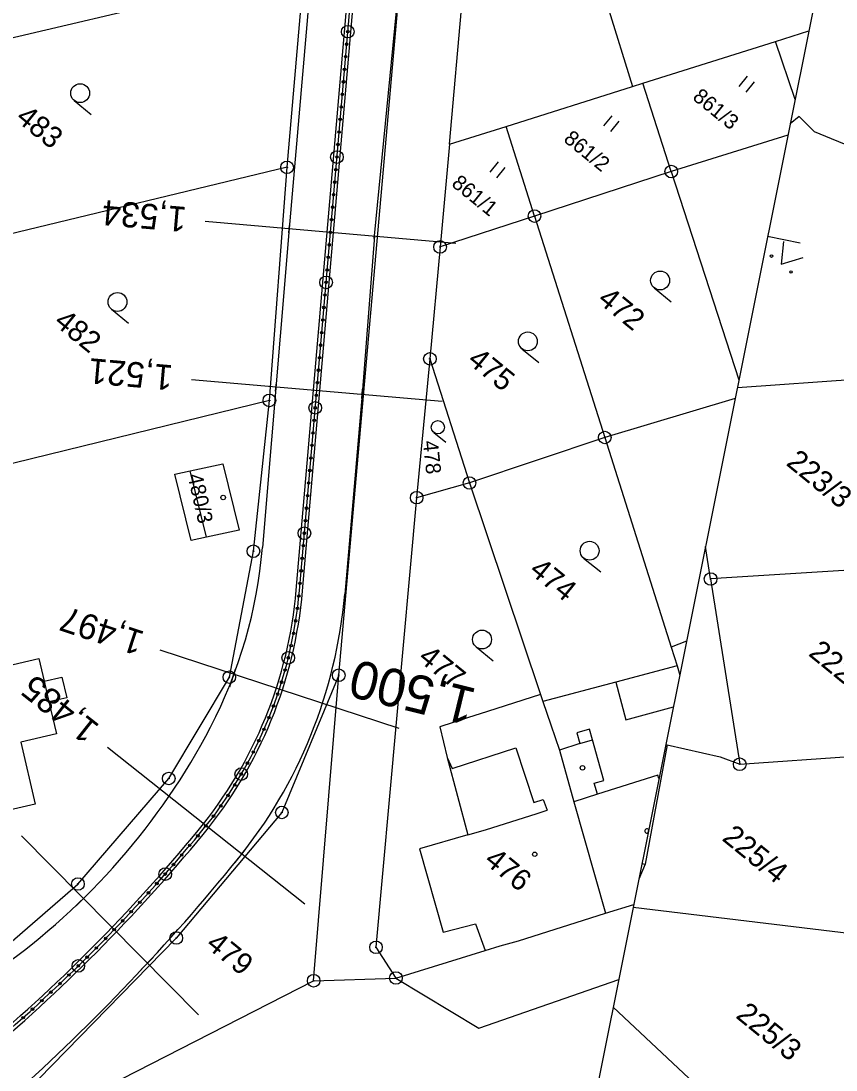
# Model space of a CAD drawing. Extents: x -548552 to -543113, y -1131925 to -1123599.
# Drawn here: x -548067.8 to -548003, y -1130269.7 to -1130186.3 of the extents above; entities that cross this region are included whole.
import ezdxf

# ---------------------------------------------------------------- set-up
doc = ezdxf.new("R2010")
doc.units = 0
for name, color, linetype in [('Hranice parcel', 7, 'Continuous'), ('Parcelní čísla', 7, 'Continuous'), ('Poz předměty', 7, 'Continuous'), ('Profile', 7, 'Continuous'), ('PROFILY', 7, 'Continuous'), ('STANIČENÍ', 7, 'Continuous'), ('STANIČENÍ PROFILY', 7, 'Continuous'), ('Vnitřní kresba', 7, 'Continuous'), ('Značky bodu BP', 7, 'Continuous'), ('Značky budov', 7, 'Continuous'), ('Značky kultur', 7, 'Continuous')]:
    doc.layers.add(name, color=color, linetype=linetype)

msp = doc.modelspace()

# ---------------------------------------------------------------- linework, layer by layer
at = {"layer": 'Hranice parcel'}
for p, q in [((-548033.748, -1130196.121), (-548032.291, -1130179.909)), ((-548045.268, -1130182.222), (-548085.244, -1130191.601)), ((-548046.64, -1130197.95), (-548045.268, -1130182.222)), ((-548007.844, -1130187.945), (-548005.181, -1130187.105)), ((-548018.386, -1130191.275), (-548007.844, -1130187.945)), ((-548006.276, -1130192.568), (-548007.844, -1130187.945)), ((-548029.238, -1130194.701), (-548019.184, -1130191.528)), ((-548019.184, -1130191.528), (-548018.386, -1130191.275)), ((-548016.113, -1130198.286), (-548018.386, -1130191.275)), ((-548033.748, -1130196.121), (-548029.238, -1130194.701)), ((-548026.982, -1130201.827), (-548029.238, -1130194.701)), ((-548006.844, -1130195.397), (-548016.113, -1130198.286)), ((-548001.454, -1130196.473), (-548004.739, -1130195.139)), ((-548033.748, -1130196.121), (-548034.486, -1130204.278)), ((-548046.64, -1130197.95), (-548075.622, -1130204.948)), ((-548048.046, -1130216.475), (-548046.64, -1130197.95)), ((-548016.113, -1130198.286), (-548026.982, -1130201.827)), ((-548016.113, -1130198.286), (-548010.742, -1130214.843)), ((-548026.982, -1130201.827), (-548034.486, -1130204.278)), ((-548026.982, -1130201.827), (-548021.396, -1130219.417)), ((-548034.486, -1130204.278), (-548035.291, -1130213.167)), ((-548035.291, -1130213.167), (-548036.346, -1130224.2)), ((-548035.291, -1130213.167), (-548032.144, -1130223.031)), ((-548010.86, -1130215.434), (-548000.239, -1130214.695)), ((-548048.046, -1130216.475), (-548075.117, -1130223.106)), ((-548011.035, -1130216.308), (-548021.396, -1130219.417)), ((-548021.396, -1130219.417), (-548032.144, -1130223.031)), ((-548021.396, -1130219.417), (-548016.126, -1130236.08)), ((-548032.144, -1130223.031), (-548036.346, -1130224.2)), ((-548032.144, -1130223.031), (-548026.511, -1130239.835)), ((-548012.988, -1130230.66), (-548013.395, -1130228.081)), ((-547988.024, -1130229.07), (-548012.988, -1130230.66)), ((-548012.988, -1130230.66), (-548010.674, -1130245.379)), ((-548014.904, -1130235.608), (-548016.126, -1130236.08)), ((-548016.126, -1130236.08), (-548015.655, -1130237.56)), ((-548044.53, -1130262.587), (-548042.539, -1130238.309)), ((-548026.511, -1130239.835), (-548026.327, -1130240.385)), ((-548010.674, -1130245.379), (-548001.577, -1130244.741)), ((-547998.027, -1130259.319), (-548019.145, -1130256.769)), ((-548037.992, -1130262.367), (-548030.915, -1130260.187)), ((-548072.972, -1130277.092), (-548044.53, -1130262.587)), ((-548044.53, -1130262.587), (-548037.992, -1130262.367))]:
    msp.add_line(p, q, dxfattribs=at)
for points in [[(-548042.539, -1130238.309), (-548033.342, -1130134.206), (-548027.481, -1130069.111), (-548024.869, -1130039.574), (-548023.736, -1130027.701), (-548024.259, -1130024.528), (-548026.746, -1130012.635), (-548032.196, -1129998.457), (-548039.765, -1129984.964)], [(-548032.291, -1130179.909), (-548023.886, -1130177.096), (-548025.091, -1130172.876), (-548012.83, -1130168.908), (-548008.896, -1130181.194), (-548021.189, -1130185.122), (-548019.184, -1130191.528)], [(-548004.739, -1130195.139), (-548005.938, -1130193.903), (-548006.665, -1130194.506)], [(-548082.316, -1130271.415), (-548063.263, -1130254.897), (-548056.045, -1130246.512), (-548051.23, -1130238.465), (-548049.317, -1130228.453), (-548048.046, -1130216.475)], [(-548054.347, -1130222.072), (-548051.739, -1130221.515), (-548050.447, -1130226.785), (-548053.056, -1130227.342), (-548054.259, -1130227.6), (-548055.558, -1130222.324), (-548054.347, -1130222.072)], [(-548036.346, -1130224.2), (-548039.577, -1130259.927), (-548037.992, -1130262.367)], [(-548067.804, -1130243.626), (-548066.662, -1130248.542), (-548076.655, -1130250.849), (-548079.17, -1130239.94), (-548069.191, -1130237.634), (-548066.358, -1130236.975), (-548065.947, -1130238.781), (-548064.53, -1130238.451), (-548064.154, -1130240.112), (-548065.564, -1130240.433), (-548064.972, -1130242.967), (-548067.804, -1130243.626)], [(-548015.655, -1130237.56), (-548020.521, -1130238.846), (-548026.327, -1130240.385)], [(-548015.655, -1130237.56), (-548015.443, -1130238.296)], [(-548042.539, -1130238.309), (-548047.062, -1130249.212), (-548055.446, -1130259.188), (-548072.972, -1130277.092)], [(-548026.511, -1130239.835), (-548030.723, -1130241.189), (-548032.305, -1130241.706), (-548034.501, -1130242.406), (-548033.926, -1130244.835), (-548032.279, -1130251), (-548036.119, -1130252.103), (-548034.227, -1130258.727), (-548031.664, -1130258.067), (-548030.915, -1130260.187)], [(-548026.327, -1130240.385), (-548025.697, -1130242.239), (-548025.006, -1130244.273), (-548023.849, -1130248.362), (-548021.352, -1130257.22)], [(-548016.433, -1130243.835), (-548018.185, -1130253.332), (-548018.691, -1130254.503)], [(-548016.548, -1130243.809), (-548016.433, -1130243.835)], [(-548016.433, -1130243.835), (-548012.227, -1130244.784), (-548010.674, -1130245.379)], [(-548021.352, -1130257.22), (-548019.096, -1130256.523)], [(-548030.915, -1130260.187), (-548029.709, -1130259.815), (-548028.264, -1130259.418), (-548021.352, -1130257.22)], [(-548020.732, -1130264.685), (-548009.966, -1130274.783)]]:
    msp.add_lwpolyline(points, dxfattribs=at)
at = {"layer": 'Poz předměty'}
for p, q in [((-548045.909, -1130231.549), (-548029.039, -1130036.611)), ((-548045.411, -1130231.592), (-548028.541, -1130036.654)), ((-548044.159, -1130175.947), (-548046.465, -1130202.821)), ((-548039.7, -1130203.406), (-548037.055, -1130176.562)), ((-548046.465, -1130202.821), (-548048.597, -1130228.168)), ((-548039.7, -1130203.406), (-548040.678, -1130215.988)), ((-548040.678, -1130215.988), (-548042.063, -1130231.874))]:
    msp.add_line(p, q, dxfattribs=at)
for centre, radius, start, end in [((-548086.208, -1130225.003), 37.743, 332.49077, 355.18998), ((-548080.53, -1130228.553), 34.75, 320.53715, 355.05376), ((-548080.53, -1130228.553), 35, 320.53715, 355.05376), ((-548080.53, -1130228.553), 35.25, 320.53715, 355.05376), ((-548080.737, -1130228.502), 38.82, 320.93302, 355.01788), ((-548100.597, -1130217.509), 53.966, 305.24777, 332.49077), ((-548157.702, -1130165.021), 134.709, 309.85025, 320.53715), ((-548157.702, -1130165.021), 134.959, 309.85025, 320.53715), ((-548157.702, -1130165.021), 135.209, 309.85025, 320.53715), ((-548177.245, -1130150.164), 163.121, 311.83002, 320.93302)]:
    msp.add_arc(centre, radius, start, end, dxfattribs=at)
at = {"layer": 'Profile'}
for p, q in [((-548003.516, -1130178.797), (-548026.625, -1130294.081)), ((-548003.516, -1130178.797), (-548026.625, -1130294.081)), ((-548003.516, -1130178.797), (-548026.625, -1130294.081)), ((-548005.871, -1130203.979), (-548008.46, -1130203.46))]:
    msp.add_line(p, q, dxfattribs=at)
at = {"layer": 'PROFILY'}
for points in [[(-548053.159, -1130202.241), (-548033.234, -1130203.966)], [(-548054.247, -1130214.813), (-548034.322, -1130216.538)], [(-548056.762, -1130236.298), (-548037.754, -1130242.518)], [(-548060.902, -1130244.034), (-548045.236, -1130256.466)], [(-548067.752, -1130251.081), (-548053.681, -1130265.295)]]:
    msp.add_lwpolyline(points, dxfattribs=at)
at = {"layer": 'STANIČENÍ'}
for p, q in [((-548045.66, -1130231.571), (-548028.79, -1130036.633)), ((-548046.494, -1130203.159), (-548046.443, -1130202.572)), ((-548039.718, -1130203.614), (-548039.686, -1130203.253)), ((-548047.552, -1130215.739), (-548047.493, -1130215.056)), ((-548040.706, -1130216.307), (-548040.643, -1130215.577)), ((-548063.411, -1130256.633), (-548062.393, -1130255.626)), ((-548058.229, -1130261.677), (-548057.282, -1130260.74))]:
    msp.add_line(p, q, dxfattribs=at)
for centre, radius in [((-548041.818, -1130187.172), 0.5), ((-548041.818, -1130187.172), 0.1), ((-548041.904, -1130188.168), 0.1), ((-548041.99, -1130189.165), 0.1), ((-548042.077, -1130190.161), 0.1), ((-548042.163, -1130191.157), 0.1), ((-548042.249, -1130192.153), 0.1), ((-548042.335, -1130193.15), 0.1), ((-548042.421, -1130194.146), 0.1), ((-548042.508, -1130195.142), 0.1), ((-548042.68, -1130197.135), 0.5), ((-548042.594, -1130196.138), 0.1), ((-548042.68, -1130197.135), 0.1), ((-548042.766, -1130198.131), 0.1), ((-548042.853, -1130199.127), 0.1), ((-548042.939, -1130200.124), 0.1), ((-548043.025, -1130201.12), 0.1), ((-548043.111, -1130202.116), 0.1), ((-548043.197, -1130203.112), 0.1), ((-548043.284, -1130204.109), 0.1), ((-548043.37, -1130205.105), 0.1), ((-548043.542, -1130207.097), 0.5), ((-548043.456, -1130206.101), 0.1), ((-548043.542, -1130207.097), 0.1), ((-548043.629, -1130208.094), 0.1), ((-548043.715, -1130209.09), 0.1), ((-548043.801, -1130210.086), 0.1), ((-548043.887, -1130211.083), 0.1), ((-548043.973, -1130212.079), 0.1), ((-548044.06, -1130213.075), 0.1), ((-548044.146, -1130214.071), 0.1), ((-548044.232, -1130215.068), 0.1), ((-548044.318, -1130216.064), 0.1), ((-548044.405, -1130217.06), 0.5), ((-548044.405, -1130217.06), 0.1), ((-548044.491, -1130218.057), 0.1), ((-548044.577, -1130219.053), 0.1), ((-548044.663, -1130220.049), 0.1), ((-548044.749, -1130221.045), 0.1), ((-548044.836, -1130222.042), 0.1), ((-548044.922, -1130223.038), 0.1), ((-548045.008, -1130224.034), 0.1), ((-548045.094, -1130225.03), 0.1), ((-548045.181, -1130226.027), 0.1), ((-548045.267, -1130227.023), 0.5), ((-548045.267, -1130227.023), 0.1), ((-548045.353, -1130228.019), 0.1), ((-548045.439, -1130229.016), 0.1), ((-548045.525, -1130230.012), 0.1), ((-548045.612, -1130231.008), 0.1), ((-548045.701, -1130232.004), 0.1), ((-548045.813, -1130232.998), 0.1), ((-548045.955, -1130233.988), 0.1), ((-548046.124, -1130234.973), 0.1), ((-548046.321, -1130235.953), 0.1), ((-548046.547, -1130236.928), 0.5), ((-548046.547, -1130236.928), 0.1), ((-548046.8, -1130237.895), 0.1), ((-548047.08, -1130238.855), 0.1), ((-548047.388, -1130239.806), 0.1), ((-548047.723, -1130240.748), 0.1), ((-548048.085, -1130241.681), 0.1), ((-548048.473, -1130242.602), 0.1), ((-548048.888, -1130243.512), 0.1), ((-548049.328, -1130244.41), 0.1), ((-548050.285, -1130246.166), 0.5), ((-548049.794, -1130245.295), 0.1), ((-548050.285, -1130246.166), 0.1), ((-548050.8, -1130247.023), 0.1), ((-548051.34, -1130247.865), 0.1), ((-548051.904, -1130248.691), 0.1), ((-548052.491, -1130249.5), 0.1), ((-548053.733, -1130251.068), 0.1), ((-548053.1, -1130250.293), 0.1), ((-548054.387, -1130251.824), 0.1), ((-548055.014, -1130252.595), 0.1), ((-548055.667, -1130253.354), 0.1), ((-548056.325, -1130254.108), 0.5), ((-548056.325, -1130254.108), 0.1), ((-548056.989, -1130254.859), 0.1), ((-548057.651, -1130255.596), 0.1), ((-548058.343, -1130256.354), 0.1), ((-548059.034, -1130257.1), 0.1), ((-548060.383, -1130258.525), 0.1), ((-548059.711, -1130257.82), 0.1), ((-548061.057, -1130259.221), 0.1), ((-548061.801, -1130259.979), 0.1), ((-548063.231, -1130261.402), 0.5), ((-548062.53, -1130260.71), 0.1), ((-548063.231, -1130261.402), 0.1), ((-548063.979, -1130262.129), 0.1), ((-548065.417, -1130263.497), 0.1), ((-548064.686, -1130262.807), 0.1), ((-548066.133, -1130264.163), 0.1), ((-548066.87, -1130264.839), 0.1), ((-548067.616, -1130265.513), 0.1)]:
    msp.add_circle(centre, radius, dxfattribs=at)
for radius, start, end in [(31.21, 339.99362, 342.91333), (38.63, 320.38987, 322.44089)]:
    msp.add_arc((-548080.53, -1130228.553), radius, start, end, dxfattribs=at)
at = {"layer": 'Vnitřní kresba'}
for p, q in [((-548053.056, -1130227.342), (-548054.347, -1130222.072)), ((-548065.947, -1130238.781), (-548065.564, -1130240.433)), ((-548020.521, -1130238.846), (-548019.73, -1130241.85)), ((-548019.73, -1130241.85), (-548015.946, -1130240.808)), ((-548022.619, -1130242.593), (-548023.621, -1130242.873)), ((-548022.384, -1130243.429), (-548022.619, -1130242.593)), ((-548023.621, -1130242.873), (-548023.375, -1130243.744)), ((-548023.375, -1130243.744), (-548022.384, -1130243.429)), ((-548021.485, -1130246.664), (-548022.384, -1130243.429)), ((-548028.46, -1130244.064), (-548027.04, -1130248.432)), ((-548023.375, -1130243.744), (-548025.006, -1130244.273)), ((-548022.243, -1130246.897), (-548021.485, -1130246.664)), ((-548017.178, -1130246.238), (-548021.969, -1130247.765)), ((-548017.092, -1130246.522), (-548017.178, -1130246.238)), ((-548021.969, -1130247.765), (-548022.243, -1130246.897)), ((-548027.04, -1130248.432), (-548026.284, -1130248.185)), ((-548026.284, -1130248.185), (-548025.976, -1130249.042)), ((-548021.969, -1130247.765), (-548023.849, -1130248.362)), ((-548030.884, -1130250.602), (-548026.768, -1130249.286)), ((-548026.768, -1130249.286), (-548025.976, -1130249.042)), ((-548032.279, -1130251), (-548030.884, -1130250.602)), ((-548018.443, -1130253.266), (-548018.185, -1130253.332)), ((-548037.992, -1130262.367), (-548031.416, -1130266.343)), ((-548031.416, -1130266.343), (-548020.292, -1130262.49))]:
    msp.add_line(p, q, dxfattribs=at)
msp.add_lwpolyline([(-548033.926, -1130244.835), (-548033.523, -1130245.718), (-548028.46, -1130244.064)], dxfattribs=at)
at = {"layer": 'Značky bodu BP'}
for centre, radius in [((-548046.64, -1130197.95), 0.5), ((-548046.64, -1130197.95), 0.0303), ((-548016.113, -1130198.286), 0.5), ((-548016.113, -1130198.286), 0.0303), ((-548026.982, -1130201.827), 0.5), ((-548026.982, -1130201.827), 0.0303), ((-548034.486, -1130204.278), 0.5), ((-548034.486, -1130204.278), 0.0303), ((-548035.291, -1130213.167), 0.5), ((-548035.291, -1130213.167), 0.0303), ((-548048.046, -1130216.474), 0.5), ((-548048.046, -1130216.474), 0.0303), ((-548021.396, -1130219.417), 0.5), ((-548021.396, -1130219.417), 0.0303), ((-548032.144, -1130223.031), 0.5), ((-548032.144, -1130223.031), 0.0303), ((-548036.346, -1130224.2), 0.5), ((-548036.346, -1130224.2), 0.0303), ((-548049.317, -1130228.453), 0.5), ((-548049.317, -1130228.453), 0.0303), ((-548012.988, -1130230.66), 0.5), ((-548012.988, -1130230.66), 0.0303), ((-548051.23, -1130238.464), 0.5), ((-548051.23, -1130238.464), 0.0303), ((-548042.539, -1130238.309), 0.5), ((-548042.539, -1130238.309), 0.0303), ((-548010.674, -1130245.379), 0.5), ((-548010.674, -1130245.379), 0.0303), ((-548056.044, -1130246.512), 0.5), ((-548056.044, -1130246.512), 0.0303), ((-548047.061, -1130249.212), 0.5), ((-548047.061, -1130249.212), 0.0303), ((-548063.262, -1130254.897), 0.5), ((-548063.262, -1130254.897), 0.0303), ((-548055.446, -1130259.188), 0.5), ((-548055.446, -1130259.188), 0.0303), ((-548039.577, -1130259.927), 0.5), ((-548039.577, -1130259.927), 0.0303), ((-548044.53, -1130262.586), 0.5), ((-548044.53, -1130262.586), 0.0303), ((-548037.992, -1130262.366), 0.5), ((-548037.992, -1130262.366), 0.0303)]:
    msp.add_circle(centre, radius, dxfattribs=at)
at = {"layer": 'Značky budov'}
msp.add_line((-548017.957, -1130250.841), (-548017.903, -1130250.571), dxfattribs=at)
for centre in [(-548051.719, -1130224.187), (-548023.169, -1130245.665), (-548026.96, -1130252.534)]:
    msp.add_circle(centre, 0.175, dxfattribs=at)
msp.add_arc((-548018.036, -1130250.684), 0.175, 40.47902, 296.85173, dxfattribs=at)
at = {"layer": 'Značky kultur'}
for p, q in [((-548010.718, -1130191.524), (-548010.055, -1130190.71)), ((-548010.174, -1130191.967), (-548009.511, -1130191.153)), ((-548063.561, -1130192.64), (-548062.204, -1130193.745)), ((-548021.464, -1130194.662), (-548020.801, -1130193.848)), ((-548020.921, -1130195.105), (-548020.258, -1130194.291)), ((-548030.515, -1130198.33), (-548029.851, -1130197.516)), ((-548029.971, -1130198.773), (-548029.308, -1130197.959)), ((-548017.475, -1130207.521), (-548016.118, -1130208.626)), ((-548060.594, -1130209.232), (-548059.237, -1130210.337)), ((-548027.983, -1130212.362), (-548026.626, -1130213.467)), ((-548034.989, -1130219.011), (-548034.039, -1130219.785)), ((-548023.078, -1130228.998), (-548021.721, -1130230.103)), ((-548031.626, -1130236.055), (-548030.269, -1130237.16))]:
    msp.add_line(p, q, dxfattribs=at)
msp.add_lwpolyline([(-548007.197, -1130203.84), (-548007.37, -1130205.635), (-548005.646, -1130205.103)], dxfattribs=at)
for centre, radius in [((-548063.087, -1130192.058), 0.75), ((-548008.145, -1130205.003), 0.1), ((-548017.001, -1130206.94), 0.75), ((-548006.594, -1130206.267), 0.1), ((-548060.12, -1130208.65), 0.75), ((-548027.509, -1130211.78), 0.75), ((-548034.657, -1130218.604), 0.525), ((-548022.604, -1130228.416), 0.75), ((-548031.152, -1130235.473), 0.75)]:
    msp.add_circle(centre, radius, dxfattribs=at)

# ---------------------------------------------------------------- texts
at = {"layer": 'Parcelní čísla'}
for s, height, rotation, p in [('861/3', 1.2, 320.83233, (-548014.492, -1130192.5)), ('483', 1.7, 320.83233, (-548068.288, -1130194.18)), ('861/2', 1.2, 320.83233, (-548024.742, -1130195.835)), ('861/1', 1.2, 320.83233, (-548033.649, -1130199.375)), ('472', 1.7, 320.83233, (-548022.054, -1130208.627)), ('482', 1.7, 320.83233, (-548065.252, -1130210.403)), ('475', 1.7, 320.83233, (-548032.394, -1130213.451)), ('478', 1.2, 275.83233, (-548035.849, -1130219.72)), ('223/3', 1.7, 320.83233, (-548007.064, -1130221.556)), ('480/3', 1.2, 282.83233, (-548054.562, -1130222.425)), ('474', 1.7, 320.83233, (-548027.483, -1130230.143)), ('222/2', 1.7, 320.83233, (-548005.284, -1130236.691)), ('477', 1.7, 320.83233, (-548036.313, -1130237.087)), ('225/4', 1.7, 320.83233, (-548012.158, -1130251.367)), ('476', 1.7, 320.83233, (-548031.064, -1130253.19)), ('479', 1.7, 320.83233, (-548053.177, -1130259.863)), ('225/3', 1.7, 320.83233, (-548011.066, -1130265.465))]:
    msp.add_text(s, height=height, rotation=rotation, dxfattribs=at).set_placement(p)
at = {"layer": 'STANIČENÍ'}
msp.add_text('1,500', height=3, rotation=166.18514, dxfattribs=at).set_placement((-548031.458, -1130239.421))
at = {"layer": 'STANIČENÍ PROFILY'}
for s, rotation, p in [('1,534', 175.05376, (-548054.568, -1130201.116)), ('1,521', 175.05376, (-548055.656, -1130213.688)), ('1,497', 161.87968, (-548057.877, -1130234.881)), ('1,485', 141.56659, (-548061.456, -1130242.318))]:
    msp.add_text(s, height=2, rotation=rotation, dxfattribs=at).set_placement(p)

doc.saveas('drawing.dxf')
